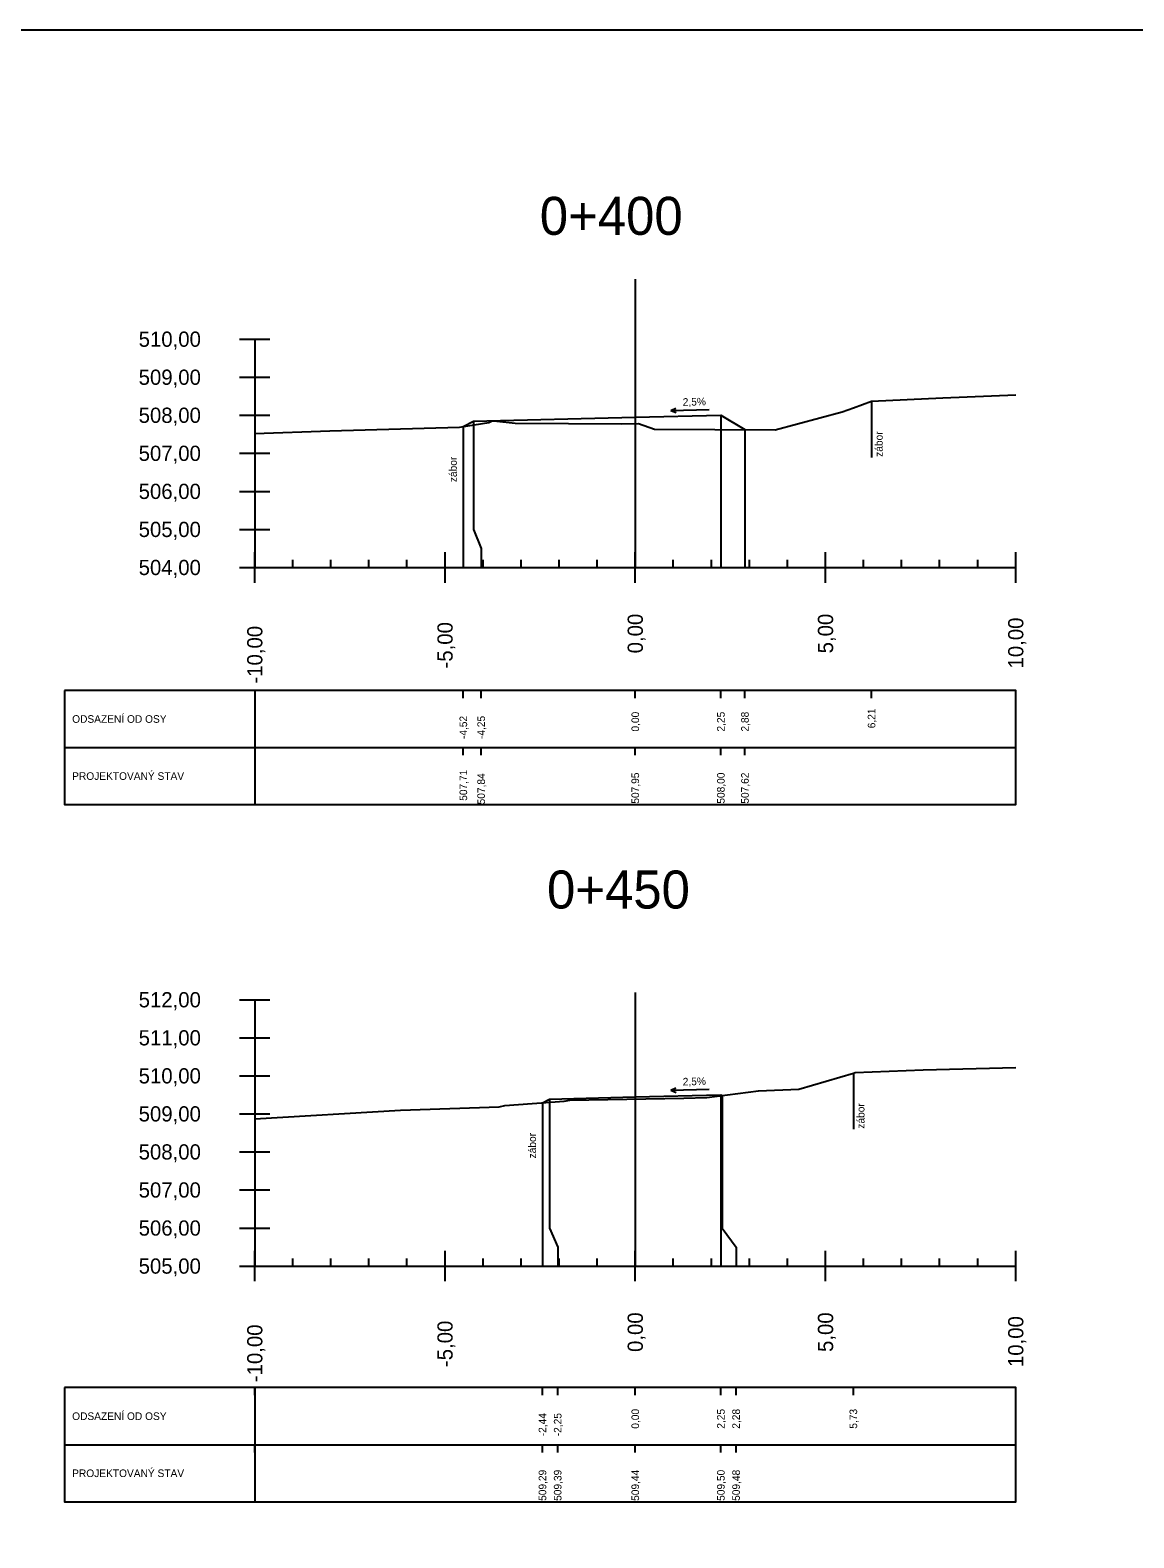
# Model space of a CAD drawing. Extents: x -631407 to -631215, y -1089700 to -1088598.
# Drawn here: x -631374.65 to -631345.64, y -1089150.59 to -1089110.96 of the extents above; entities that cross this region are included whole.
import ezdxf

# ---------------------------------------------------------------- set-up
doc = ezdxf.new("R2010")
doc.units = 0
for name, color, linetype in [('08_LEGENDA_HV', 7, 'Continuous'), ('59', 7, 'Continuous'), ('NIVELETA_VYSKY', 7, 'Continuous'), ('REZ_BODY', 7, 'Continuous'), ('REZ_ODSTUPY', 7, 'Continuous'), ('REZ_POPIS', 7, 'Continuous'), ('REZ_RAMY', 7, 'Continuous'), ('REZ_STANICENI', 7, 'Continuous'), ('REZ_SVISLE', 7, 'Continuous'), ('REZ_TENKA', 7, 'Continuous'), ('REZ_TLUSTA', 7, 'Continuous'), ('TABULKA_POPIS', 7, 'Continuous'), ('TEREN', 7, 'Continuous'), ('zábor', 7, 'Continuous')]:
    doc.layers.add(name, color=color, linetype=linetype)

msp = doc.modelspace()

# ---------------------------------------------------------------- linework, layer by layer
at = {"layer": '08_LEGENDA_HV'}
msp.add_lwpolyline([(-631215.384, -1089270.801), (-631215.384, -1089110.964), (-631407.014, -1089110.964), (-631407.014, -1089270.801)], close=True, dxfattribs=at)
at = {"layer": '59'}
for p, q in [((-631369.144, -1089119.086), (-631368.344, -1089119.086)), ((-631368.744, -1089119.086), (-631368.744, -1089125.086)), ((-631369.144, -1089120.086), (-631368.344, -1089120.086)), ((-631369.144, -1089121.086), (-631368.344, -1089121.086)), ((-631369.144, -1089122.086), (-631368.344, -1089122.086)), ((-631369.144, -1089123.086), (-631368.344, -1089123.086)), ((-631369.144, -1089124.086), (-631368.344, -1089124.086)), ((-631369.144, -1089125.086), (-631368.344, -1089125.086)), ((-631369.144, -1089136.448), (-631368.344, -1089136.448)), ((-631368.744, -1089136.448), (-631368.744, -1089143.448)), ((-631369.144, -1089137.448), (-631368.344, -1089137.448)), ((-631369.144, -1089138.448), (-631368.344, -1089138.448)), ((-631369.144, -1089139.448), (-631368.344, -1089139.448)), ((-631369.144, -1089140.448), (-631368.344, -1089140.448)), ((-631369.144, -1089141.448), (-631368.344, -1089141.448)), ((-631369.144, -1089142.448), (-631368.344, -1089142.448)), ((-631369.144, -1089143.448), (-631368.344, -1089143.448))]:
    msp.add_line(p, q, dxfattribs=at)
at = {"layer": 'REZ_RAMY'}
for p, q in [((-631373.744, -1089128.319), (-631373.744, -1089131.319)), ((-631368.744, -1089128.319), (-631368.744, -1089131.319)), ((-631363.263, -1089128.519), (-631363.263, -1089128.319)), ((-631362.794, -1089128.519), (-631362.794, -1089128.319)), ((-631358.744, -1089128.519), (-631358.744, -1089128.319)), ((-631356.494, -1089128.519), (-631356.494, -1089128.319)), ((-631355.861, -1089128.519), (-631355.861, -1089128.319)), ((-631352.534, -1089128.519), (-631352.534, -1089128.319)), ((-631373.744, -1089129.819), (-631348.744, -1089129.819)), ((-631363.263, -1089130.019), (-631363.263, -1089129.819)), ((-631362.794, -1089130.019), (-631362.794, -1089129.819)), ((-631358.744, -1089130.019), (-631358.744, -1089129.819)), ((-631356.494, -1089130.019), (-631356.494, -1089129.819)), ((-631355.861, -1089130.019), (-631355.861, -1089129.819)), ((-631373.744, -1089146.644), (-631373.744, -1089149.644)), ((-631368.744, -1089146.644), (-631368.744, -1089149.644)), ((-631368.744, -1089146.844), (-631368.744, -1089146.644)), ((-631361.183, -1089146.844), (-631361.183, -1089146.644)), ((-631360.783, -1089146.844), (-631360.783, -1089146.644)), ((-631358.744, -1089146.844), (-631358.744, -1089146.644)), ((-631356.494, -1089146.844), (-631356.494, -1089146.644)), ((-631356.094, -1089146.844), (-631356.094, -1089146.644)), ((-631353.012, -1089146.844), (-631353.012, -1089146.644)), ((-631373.744, -1089148.144), (-631348.744, -1089148.144)), ((-631368.744, -1089148.344), (-631368.744, -1089148.144)), ((-631361.183, -1089148.344), (-631361.183, -1089148.144)), ((-631360.783, -1089148.344), (-631360.783, -1089148.144)), ((-631358.744, -1089148.344), (-631358.744, -1089148.144)), ((-631356.494, -1089148.344), (-631356.494, -1089148.144)), ((-631356.094, -1089148.344), (-631356.094, -1089148.144))]:
    msp.add_line(p, q, dxfattribs=at)
for points in [[(-631373.744, -1089128.319), (-631373.744, -1089131.319), (-631348.744, -1089131.319), (-631348.744, -1089128.319)], [(-631373.744, -1089146.644), (-631373.744, -1089149.644), (-631348.744, -1089149.644), (-631348.744, -1089146.644)]]:
    msp.add_lwpolyline(points, close=True, dxfattribs=at)
at = {"layer": 'REZ_SVISLE'}
for points in [[(-631356.494, -1089121.083), (-631356.494, -1089124.086), (-631356.494, -1089124.586), (-631356.494, -1089125.086)], [(-631363.263, -1089121.38), (-631363.263, -1089124.086), (-631363.263, -1089124.586), (-631363.263, -1089125.086)], [(-631362.994, -1089121.245), (-631362.994, -1089124.086), (-631362.794, -1089124.586), (-631362.794, -1089125.086)], [(-631358.744, -1089121.139), (-631358.744, -1089124.086), (-631358.744, -1089124.586), (-631358.744, -1089125.086)], [(-631355.861, -1089121.463), (-631355.861, -1089124.086), (-631355.861, -1089124.586), (-631355.861, -1089125.086)], [(-631361.183, -1089139.155), (-631361.183, -1089142.448), (-631361.183, -1089142.948), (-631361.183, -1089143.448)], [(-631360.994, -1089139.06), (-631360.994, -1089142.448), (-631360.783, -1089142.948), (-631360.783, -1089143.448)], [(-631358.744, -1089139.004), (-631358.744, -1089142.448), (-631358.744, -1089142.948), (-631358.744, -1089143.448)], [(-631356.494, -1089138.948), (-631356.494, -1089142.448), (-631356.494, -1089142.948), (-631356.494, -1089143.448)], [(-631356.461, -1089138.967), (-631356.461, -1089142.448), (-631356.094, -1089142.948), (-631356.094, -1089143.448)]]:
    msp.add_lwpolyline(points, dxfattribs=at)
at = {"layer": 'REZ_TENKA'}
for p, q in [((-631367.744, -1089125.086), (-631367.744, -1089124.886)), ((-631366.744, -1089125.086), (-631366.744, -1089124.886)), ((-631365.744, -1089125.086), (-631365.744, -1089124.886)), ((-631364.744, -1089125.086), (-631364.744, -1089124.886)), ((-631362.744, -1089125.086), (-631362.744, -1089124.886)), ((-631361.744, -1089125.086), (-631361.744, -1089124.886)), ((-631360.744, -1089125.086), (-631360.744, -1089124.886)), ((-631359.744, -1089125.086), (-631359.744, -1089124.886)), ((-631357.744, -1089125.086), (-631357.744, -1089124.886)), ((-631356.744, -1089125.086), (-631356.744, -1089124.886)), ((-631355.744, -1089125.086), (-631355.744, -1089124.886)), ((-631354.744, -1089125.086), (-631354.744, -1089124.886)), ((-631352.744, -1089125.086), (-631352.744, -1089124.886)), ((-631351.744, -1089125.086), (-631351.744, -1089124.886)), ((-631350.744, -1089125.086), (-631350.744, -1089124.886)), ((-631349.744, -1089125.086), (-631349.744, -1089124.886)), ((-631367.744, -1089143.448), (-631367.744, -1089143.248)), ((-631366.744, -1089143.448), (-631366.744, -1089143.248)), ((-631365.744, -1089143.448), (-631365.744, -1089143.248)), ((-631364.744, -1089143.448), (-631364.744, -1089143.248)), ((-631362.744, -1089143.448), (-631362.744, -1089143.248)), ((-631361.744, -1089143.448), (-631361.744, -1089143.248)), ((-631360.744, -1089143.448), (-631360.744, -1089143.248)), ((-631359.744, -1089143.448), (-631359.744, -1089143.248)), ((-631357.744, -1089143.448), (-631357.744, -1089143.248)), ((-631356.744, -1089143.448), (-631356.744, -1089143.248)), ((-631355.744, -1089143.448), (-631355.744, -1089143.248)), ((-631354.744, -1089143.448), (-631354.744, -1089143.248)), ((-631352.744, -1089143.448), (-631352.744, -1089143.248)), ((-631351.744, -1089143.448), (-631351.744, -1089143.248)), ((-631350.744, -1089143.448), (-631350.744, -1089143.248)), ((-631349.744, -1089143.448), (-631349.744, -1089143.248))]:
    msp.add_line(p, q, dxfattribs=at)
at = {"layer": 'REZ_TLUSTA'}
for p, q in [((-631358.744, -1089117.513), (-631358.744, -1089125.086)), ((-631368.744, -1089125.486), (-631368.744, -1089124.686)), ((-631363.744, -1089125.486), (-631363.744, -1089124.686)), ((-631358.744, -1089125.486), (-631358.744, -1089124.686)), ((-631353.744, -1089125.486), (-631353.744, -1089124.686)), ((-631348.744, -1089125.486), (-631348.744, -1089124.686)), ((-631368.744, -1089125.086), (-631348.744, -1089125.086)), ((-631358.744, -1089136.254), (-631358.744, -1089143.448)), ((-631368.744, -1089143.848), (-631368.744, -1089143.048)), ((-631363.744, -1089143.848), (-631363.744, -1089143.048)), ((-631358.744, -1089143.848), (-631358.744, -1089143.048)), ((-631353.744, -1089143.848), (-631353.744, -1089143.048)), ((-631348.744, -1089143.848), (-631348.744, -1089143.048)), ((-631368.744, -1089143.448), (-631348.744, -1089143.448))]:
    msp.add_line(p, q, dxfattribs=at)
at = {"layer": 'TEREN'}
for points in [[(-631368.744, -1089121.562), (-631366.767, -1089121.491), (-631363.361, -1089121.396), (-631362.595, -1089121.273), (-631362.507, -1089121.23), (-631362.386, -1089121.243), (-631361.896, -1089121.291), (-631359.098, -1089121.308), (-631358.66, -1089121.299), (-631358.236, -1089121.454), (-631355.064, -1089121.466), (-631353.303, -1089120.993), (-631353.005, -1089120.891), (-631352.534, -1089120.715), (-631350.658, -1089120.627), (-631348.744, -1089120.55)], [(-631363.263, -1089121.38), (-631362.994, -1089121.245), (-631358.744, -1089121.139), (-631356.494, -1089121.083), (-631355.861, -1089121.463)], [(-631368.744, -1089139.574), (-631364.91, -1089139.351), (-631362.323, -1089139.267), (-631362.175, -1089139.232), (-631360.616, -1089139.11), (-631360.467, -1089139.089), (-631357.463, -1089139.037), (-631356.866, -1089139.02), (-631355.504, -1089138.843), (-631354.449, -1089138.797), (-631353.012, -1089138.374), (-631352.96, -1089138.357), (-631351.179, -1089138.29), (-631348.744, -1089138.228)], [(-631361.183, -1089139.155), (-631360.994, -1089139.06), (-631358.744, -1089139.004), (-631356.494, -1089138.948), (-631356.461, -1089138.967)]]:
    msp.add_lwpolyline(points, dxfattribs=at)
at = {"layer": 'zábor'}
for p, q in [((-631357.811, -1089120.96), (-631357.674, -1089120.895)), ((-631357.811, -1089120.96), (-631356.803, -1089120.934)), ((-631357.811, -1089120.96), (-631357.671, -1089121.017)), ((-631352.534, -1089120.715), (-631352.534, -1089122.196)), ((-631353.012, -1089138.374), (-631353.012, -1089139.854)), ((-631357.811, -1089138.824), (-631357.674, -1089138.76)), ((-631357.811, -1089138.824), (-631356.803, -1089138.799)), ((-631357.811, -1089138.824), (-631357.671, -1089138.882))]:
    msp.add_line(p, q, dxfattribs=at)

# ---------------------------------------------------------------- texts
at = {"layer": 'NIVELETA_VYSKY'}
for s, p in [('507,71', (-631363.163, -1089131.219)), ('507,84', (-631362.694, -1089131.314)), ('507,95', (-631358.644, -1089131.295)), ('508,00', (-631356.394, -1089131.295)), ('507,62', (-631355.761, -1089131.295)), ('509,29', (-631361.083, -1089149.62)), ('509,39', (-631360.683, -1089149.62)), ('509,44', (-631358.644, -1089149.62)), ('509,50', (-631356.394, -1089149.62)), ('509,48', (-631355.994, -1089149.62))]:
    msp.add_text(s, height=0.2, rotation=90, dxfattribs=at).set_placement(p)
at = {"layer": 'REZ_BODY'}
for s, p in [('-4,52', (-631363.163, -1089129.597)), ('-4,25', (-631362.694, -1089129.597)), ('0,00', (-631358.644, -1089129.399)), ('2,25', (-631356.394, -1089129.399)), ('2,88', (-631355.761, -1089129.399)), ('6,21', (-631352.434, -1089129.313)), ('0,00', (-631358.644, -1089147.723)), ('2,25', (-631356.394, -1089147.723)), ('2,28', (-631355.994, -1089147.723)), ('5,73', (-631352.912, -1089147.723)), ('-2,44', (-631361.083, -1089147.921)), ('-2,25', (-631360.683, -1089147.921))]:
    msp.add_text(s, height=0.2, rotation=90, dxfattribs=at).set_placement(p)
at = {"layer": 'REZ_ODSTUPY'}
for s, p in [('-10,00', (-631368.544, -1089128.138)), ('-5,00', (-631363.544, -1089127.741)), ('0,00', (-631358.544, -1089127.344)), ('5,00', (-631353.544, -1089127.344)), ('10,00', (-631348.544, -1089127.741)), ('0,00', (-631358.544, -1089145.706)), ('5,00', (-631353.544, -1089145.706)), ('10,00', (-631348.544, -1089146.103)), ('-10,00', (-631368.544, -1089146.5)), ('-5,00', (-631363.544, -1089146.103))]:
    msp.add_text(s, height=0.4, rotation=90, dxfattribs=at).set_placement(p)
at = {"layer": 'REZ_POPIS'}
for s, p in [('510,00', (-631371.796, -1089119.286)), ('509,00', (-631371.796, -1089120.286)), ('508,00', (-631371.796, -1089121.286)), ('507,00', (-631371.796, -1089122.286)), ('506,00', (-631371.796, -1089123.286)), ('505,00', (-631371.796, -1089124.286)), ('504,00', (-631371.796, -1089125.286)), ('512,00', (-631371.796, -1089136.648)), ('511,00', (-631371.796, -1089137.648)), ('510,00', (-631371.796, -1089138.648)), ('509,00', (-631371.796, -1089139.648)), ('508,00', (-631371.796, -1089140.648)), ('507,00', (-631371.796, -1089141.648)), ('506,00', (-631371.796, -1089142.648)), ('505,00', (-631371.796, -1089143.648))]:
    msp.add_text(s, height=0.4, dxfattribs=at).set_placement(p)
at = {"layer": 'REZ_STANICENI'}
for s, p in [('0+400', (-631361.253, -1089116.344)), ('0+450', (-631361.063, -1089134.051))]:
    msp.add_text(s, height=1, dxfattribs=at).set_placement(p)
at = {"layer": 'TABULKA_POPIS'}
for s, p in [('ODSAZENÍ OD OSY', (-631373.544, -1089129.169)), ('PROJEKTOVANÝ STAV', (-631373.544, -1089130.669)), ('ODSAZENÍ OD OSY', (-631373.544, -1089147.494)), ('PROJEKTOVANÝ STAV', (-631373.544, -1089148.994))]:
    msp.add_text(s, height=0.2, dxfattribs=at).set_placement(p)
at = {"layer": 'zábor'}
for s, rotation, p in [('2,5%', 1.4321, (-631357.494, -1089120.839)), ('zábor', 90, (-631352.242, -1089122.178)), ('zábor', 90, (-631363.434, -1089122.844)), ('2,5%', 1.4321, (-631357.494, -1089138.703)), ('zábor', 90, (-631352.719, -1089139.837)), ('zábor', 90, (-631361.353, -1089140.618))]:
    msp.add_text(s, height=0.2, rotation=rotation, dxfattribs=at).set_placement(p)

doc.saveas('drawing.dxf')
